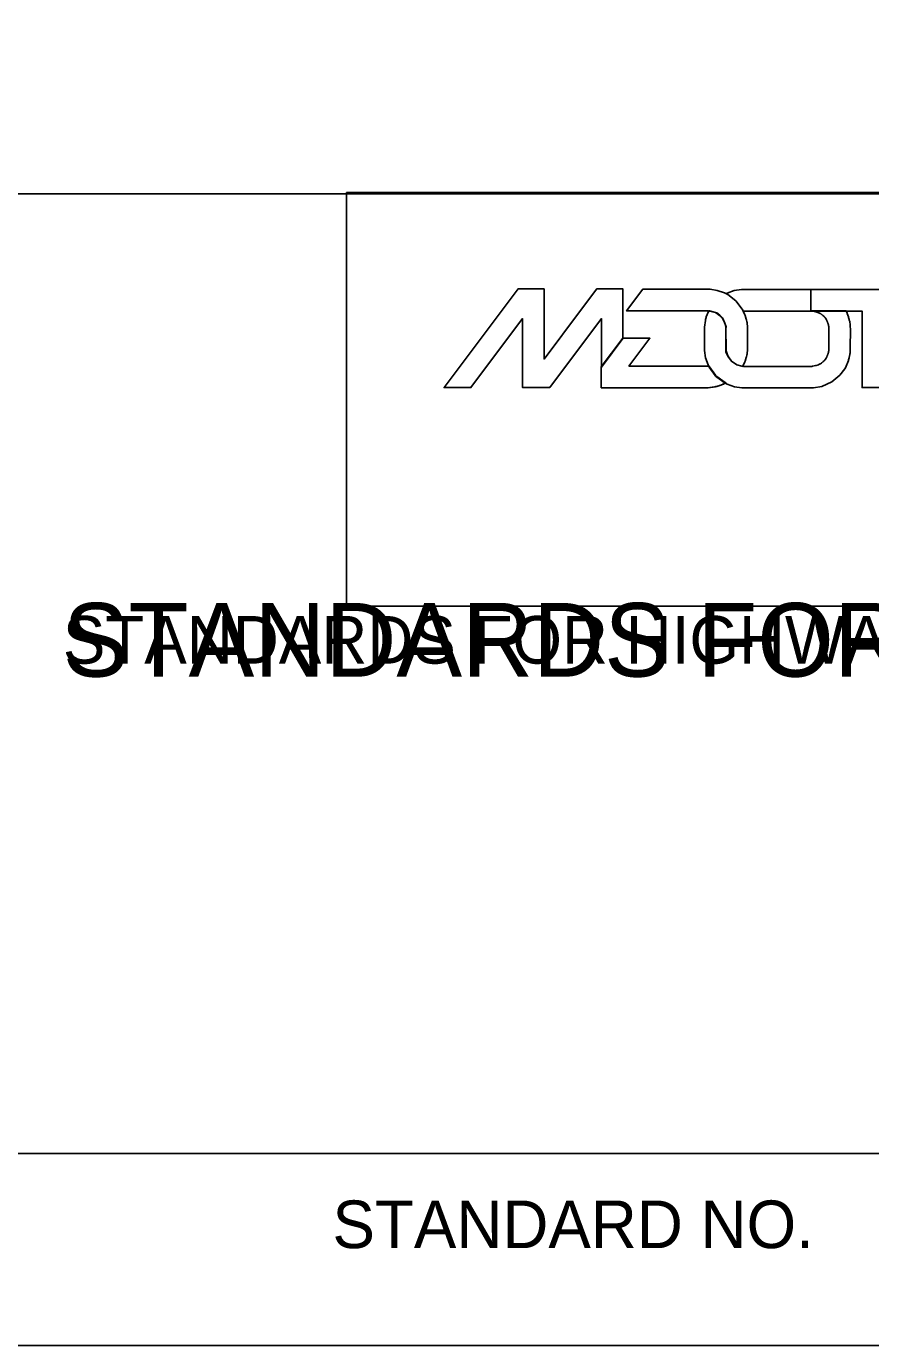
# Model space of a CAD drawing. Extents: x 0 to 1549163, y -476626 to 622136.
# Drawn here: x 3.645 to 4.709, y 5.937 to 7.599 of the extents above; entities that cross this region are included whole.
import ezdxf

# ---------------------------------------------------------------- set-up
doc = ezdxf.new("R2010")
doc.units = 0
for name, color, linetype in [('BORD-LINE', 7, 'Continuous'), ('DETL-NOTE', 7, 'Continuous'), ('MSHA-LOGO', 7, 'Continuous'), ('TTLB-TEXT', 7, 'Continuous'), ('USER-BORD', 7, 'Continuous'), ('USER-LINE', 7, 'Continuous')]:
    doc.layers.add(name, color=color, linetype=linetype)

msp = doc.modelspace()

# ---------------------------------------------------------------- linework, layer by layer
at = {"layer": 'BORD-LINE'}
msp.add_line((7.7685, 7.3883), (0.3943, 7.3883), dxfattribs=at)
at = {"layer": 'MSHA-LOGO'}
for points in [[(4.3697, 7.1699), (4.3968, 7.206), (4.3968, 7.2687), (4.3638, 7.2687), (4.3434, 7.2413), (4.2975, 7.1802), (4.2975, 7.2687), (4.2646, 7.2687), (4.1714, 7.1444), (4.2053, 7.1444), (4.2704, 7.2312), (4.2704, 7.1444), (4.3046, 7.1444), (4.3697, 7.2312)], [(4.5048, 7.2408), (4.5056, 7.2408), (4.5132, 7.2388), (4.5139, 7.2384), (4.5147, 7.238), (4.5185, 7.2352), (4.5217, 7.2319), (4.5223, 7.2312), (4.5229, 7.2303), (4.5251, 7.2256), (4.5263, 7.2205), (4.5264, 7.2195), (4.5264, 7.2195), (4.5264, 7.2193), (4.5264, 7.2193), (4.5264, 7.219), (4.5264, 7.2184), (4.5264, 7.2182), (4.5264, 7.1947), (4.5264, 7.1944), (4.5264, 7.1938), (4.5264, 7.1936), (4.5264, 7.1936), (4.5264, 7.1934), (4.5264, 7.1934), (4.5264, 7.1929), (4.5262, 7.1918), (4.5262, 7.1914), (4.5265, 7.1894), (4.5287, 7.1838), (4.5334, 7.1776), (4.5402, 7.1731), (4.5463, 7.1712), (4.5476, 7.1711), (4.5479, 7.1715), (4.5481, 7.1717), (4.5481, 7.1717), (4.5483, 7.1722), (4.5503, 7.1766), (4.5505, 7.1771), (4.5506, 7.1776), (4.552, 7.1823), (4.5522, 7.1828), (4.5522, 7.183), (4.5528, 7.1854), (4.5529, 7.1857), (4.553, 7.1864), (4.5537, 7.1927), (4.5537, 7.1948), (4.5537, 7.2179), (4.5537, 7.2202), (4.553, 7.2263), (4.5529, 7.227), (4.5528, 7.2273), (4.5523, 7.2297), (4.5522, 7.23), (4.552, 7.2304), (4.5506, 7.2352), (4.5505, 7.2356), (4.5503, 7.2361), (4.5483, 7.2406), (4.5481, 7.241), (4.5468, 7.2433), (4.5389, 7.2535), (4.5287, 7.2615), (4.5264, 7.2627), (4.5247, 7.2636), (4.5155, 7.2668), (4.5066, 7.2682), (4.5036, 7.2682), (4.4217, 7.2682), (4.4013, 7.241), (4.5036, 7.241), (4.5037, 7.2409), (4.5045, 7.2408)], [(4.5482, 7.2406), (4.5487, 7.2406), (4.5489, 7.2406), (4.6329, 7.2406), (4.633, 7.2406), (4.6333, 7.2406), (4.6334, 7.2406), (4.6335, 7.241), (4.6335, 7.268), (4.6335, 7.268), (4.633, 7.268), (4.6329, 7.268), (4.5489, 7.268), (4.5459, 7.268), (4.537, 7.2666), (4.5278, 7.2634), (4.5264, 7.2627), (4.5287, 7.2615), (4.5389, 7.2535), (4.5468, 7.2433), (4.5481, 7.241)], [(4.6335, 7.268), (4.6335, 7.2408), (4.6979, 7.2408), (4.6979, 7.1444), (4.7249, 7.1444), (4.7249, 7.2408), (4.7625, 7.2408), (4.7895, 7.2678), (4.7895, 7.268)], [(4.5269, 7.1499), (4.5268, 7.1499), (4.5266, 7.15), (4.5266, 7.1501), (4.5254, 7.1507), (4.5151, 7.1582), (4.5142, 7.1592), (4.5133, 7.1601), (4.5059, 7.1703), (4.5053, 7.1714), (4.5052, 7.1714), (4.5049, 7.1714), (4.5048, 7.1714), (4.5045, 7.1714), (4.5038, 7.1714), (4.5036, 7.1714), (4.4042, 7.1714), (4.4306, 7.2064), (4.3966, 7.2064), (4.3695, 7.1704), (4.3695, 7.1442), (4.5034, 7.1442), (4.5042, 7.1442), (4.5062, 7.1443), (4.5065, 7.1444), (4.5072, 7.1444), (4.5092, 7.1447), (4.5094, 7.1447), (4.5096, 7.1447), (4.5101, 7.1449), (4.5103, 7.1449), (4.5104, 7.1449), (4.512, 7.1452), (4.5122, 7.1452), (4.5124, 7.1452), (4.513, 7.1454), (4.5132, 7.1454), (4.5133, 7.1455), (4.5148, 7.1457), (4.5149, 7.1457), (4.515, 7.1458), (4.5158, 7.1461), (4.5159, 7.1461), (4.5161, 7.1461), (4.5174, 7.1466), (4.5175, 7.1466), (4.5176, 7.1467), (4.5184, 7.1469), (4.5185, 7.1469), (4.5186, 7.147), (4.5199, 7.1474), (4.5201, 7.1475), (4.5201, 7.1475), (4.521, 7.1478), (4.5211, 7.1478), (4.5212, 7.1479), (4.5227, 7.1485), (4.5228, 7.1485), (4.5229, 7.1485), (4.5236, 7.1488), (4.5237, 7.1489), (4.5239, 7.1489), (4.5259, 7.1499), (4.5261, 7.1501), (4.5262, 7.15), (4.5267, 7.1499)]]:
    msp.add_lwpolyline(points, close=True, dxfattribs=at)
for points in [[(4.5264, 7.205), (4.5264, 7.2179), (4.5264, 7.2183), (4.5264, 7.219), (4.5264, 7.2193), (4.5264, 7.2198), (4.5266, 7.221), (4.5266, 7.2214), (4.5265, 7.2223), (4.5231, 7.2306), (4.5226, 7.2313), (4.5221, 7.2321), (4.5188, 7.2356), (4.5149, 7.2383), (4.5141, 7.2387), (4.5133, 7.2391), (4.5058, 7.2411), (4.505, 7.2412), (4.505, 7.2411), (4.5048, 7.2408), (4.5044, 7.2402), (4.5017, 7.2334), (4.5015, 7.2327), (4.5014, 7.2325), (4.5007, 7.2301), (4.5007, 7.2298), (4.5005, 7.2288), (4.4993, 7.2206), (4.4993, 7.2179), (4.4993, 7.205), (4.4993, 7.2036)], [(4.6832, 7.2179), (4.6832, 7.2186), (4.683, 7.2206), (4.683, 7.2208), (4.683, 7.221), (4.683, 7.2217), (4.683, 7.2222), (4.6828, 7.2234), (4.6828, 7.2238), (4.6828, 7.2239), (4.6828, 7.2242), (4.6828, 7.2243), (4.6828, 7.2244), (4.6828, 7.2246), (4.6828, 7.2246), (4.6828, 7.2248), (4.6825, 7.2265), (4.6825, 7.2267), (4.6825, 7.2269), (4.6823, 7.2273), (4.6823, 7.2274), (4.6823, 7.2276), (4.6818, 7.2294), (4.6818, 7.2296), (4.6818, 7.2298), (4.6818, 7.23), (4.6817, 7.2302), (4.681, 7.2328), (4.6809, 7.2331), (4.6808, 7.2335), (4.6792, 7.2378), (4.679, 7.2382), (4.679, 7.2384), (4.6779, 7.2406), (4.6779, 7.2408), (4.6779, 7.2409), (4.6777, 7.2412), (4.6342, 7.2412), (4.6341, 7.2408), (4.6346, 7.2408), (4.6348, 7.2408), (4.635, 7.2408), (4.6355, 7.2407), (4.6356, 7.2406), (4.636, 7.2406), (4.6394, 7.2399), (4.6397, 7.2398), (4.64, 7.2397), (4.6429, 7.2387), (4.6432, 7.2386), (4.6433, 7.2385), (4.6449, 7.2376), (4.6451, 7.2375), (4.6452, 7.2375), (4.6452, 7.2375), (4.6454, 7.2375), (4.6468, 7.2366), (4.6469, 7.2365), (4.6471, 7.2364), (4.6471, 7.2363), (4.6472, 7.2362), (4.6485, 7.2353), (4.6487, 7.2351), (4.6488, 7.235), (4.649, 7.2349), (4.65, 7.2338), (4.65, 7.2337), (4.6502, 7.2336), (4.6502, 7.2336), (4.6504, 7.2334), (4.6505, 7.2333), (4.6512, 7.2325), (4.6512, 7.2324), (4.6514, 7.2322), (4.6514, 7.2322), (4.6517, 7.2317), (4.6518, 7.2317), (4.6518, 7.2316), (4.6526, 7.2306), (4.6526, 7.2305), (4.6527, 7.2304), (4.6529, 7.2299), (4.653, 7.2298), (4.6531, 7.2296), (4.6531, 7.2296), (4.6532, 7.2295), (4.6536, 7.2287), (4.6536, 7.2286), (4.6537, 7.2285), (4.6539, 7.2278), (4.654, 7.2277), (4.654, 7.2276), (4.6545, 7.2266), (4.6545, 7.2265), (4.6545, 7.2265), (4.6547, 7.2258), (4.6547, 7.2257), (4.6548, 7.2255), (4.6548, 7.2255), (4.6549, 7.2254), (4.6552, 7.2247), (4.6552, 7.2244), (4.6552, 7.2244), (4.6555, 7.2233), (4.6555, 7.2232), (4.6555, 7.223), (4.6557, 7.2224), (4.6557, 7.2222), (4.6557, 7.2221), (4.6559, 7.2211), (4.6559, 7.2208), (4.6559, 7.2206), (4.656, 7.2201), (4.656, 7.22), (4.656, 7.2194), (4.6562, 7.2182), (4.6562, 7.2177), (4.6562, 7.1941), (4.6562, 7.1936), (4.6561, 7.1921), (4.656, 7.1919), (4.656, 7.1917), (4.6559, 7.1911), (4.6559, 7.191), (4.6559, 7.1907), (4.6557, 7.1899), (4.6557, 7.1897), (4.6557, 7.1894), (4.6555, 7.1888), (4.6555, 7.1886), (4.6555, 7.1885), (4.6552, 7.1875), (4.6552, 7.1874), (4.6551, 7.1873), (4.6549, 7.1865), (4.6548, 7.1864), (4.6548, 7.1863), (4.6547, 7.1861), (4.6547, 7.186), (4.6545, 7.1855), (4.6545, 7.1854), (4.6545, 7.1853), (4.654, 7.1843), (4.654, 7.1842), (4.6539, 7.1841), (4.6537, 7.1834), (4.6536, 7.1833), (4.6536, 7.1832), (4.6532, 7.1823), (4.6531, 7.1823), (4.653, 7.1821), (4.653, 7.1821), (4.6529, 7.182), (4.6527, 7.1815), (4.6526, 7.1814), (4.6525, 7.1813), (4.6518, 7.1803), (4.6518, 7.1802), (4.6517, 7.1802), (4.6514, 7.1797), (4.6514, 7.1797), (4.6512, 7.1795), (4.6511, 7.1794), (4.6504, 7.1786), (4.6504, 7.1785), (4.6502, 7.1783), (4.6501, 7.1781), (4.65, 7.1781), (4.65, 7.178), (4.6489, 7.177), (4.6488, 7.1769), (4.6487, 7.1767), (4.6485, 7.1767), (4.6472, 7.1756), (4.6471, 7.1755), (4.6469, 7.1754), (4.6469, 7.1754), (4.6468, 7.1753), (4.6454, 7.1744), (4.6452, 7.1743), (4.6451, 7.1743), (4.6451, 7.1743), (4.6449, 7.1743), (4.6433, 7.1734), (4.6432, 7.1733), (4.6429, 7.1732), (4.64, 7.1722), (4.6397, 7.1721), (4.6394, 7.172), (4.636, 7.1713), (4.6356, 7.1712), (4.6354, 7.1712), (4.6348, 7.1711), (4.6348, 7.1711), (4.6345, 7.1711), (4.6338, 7.1711), (4.6335, 7.1711), (4.5496, 7.1711), (4.5493, 7.1711), (4.5486, 7.1711), (4.5484, 7.1711), (4.5463, 7.1712), (4.5402, 7.1731), (4.5335, 7.1778), (4.5288, 7.1845), (4.5269, 7.1905), (4.5268, 7.1926), (4.5268, 7.1929), (4.5268, 7.1937), (4.5268, 7.194), (4.5268, 7.205), (4.5264, 7.205)], [(4.4993, 7.2036), (4.4993, 7.194), (4.4993, 7.191), (4.5007, 7.182), (4.5039, 7.1728), (4.5048, 7.1711), (4.5054, 7.1699), (4.513, 7.1594), (4.5139, 7.1585), (4.5148, 7.1576), (4.5253, 7.15), (4.5264, 7.1494), (4.5281, 7.1485), (4.5373, 7.1453), (4.5463, 7.1439), (4.5492, 7.1439), (4.6332, 7.1439), (4.6367, 7.1439), (4.6472, 7.1458), (4.6596, 7.1514), (4.6699, 7.16), (4.6761, 7.1681), (4.6777, 7.1711), (4.6778, 7.1713), (4.6788, 7.1734), (4.6789, 7.1736), (4.679, 7.1741), (4.6806, 7.1784), (4.6808, 7.1788), (4.6808, 7.1791), (4.6816, 7.1817), (4.6816, 7.1819), (4.6816, 7.1821), (4.6816, 7.1823), (4.6817, 7.1824), (4.6821, 7.1843), (4.6821, 7.1845), (4.6821, 7.1847), (4.6823, 7.1851), (4.6823, 7.1852), (4.6823, 7.1854), (4.6826, 7.1871), (4.6827, 7.1872), (4.6827, 7.1873), (4.6827, 7.1875), (4.6827, 7.1876), (4.6827, 7.1877), (4.6827, 7.188), (4.6827, 7.1881), (4.6827, 7.1886), (4.6828, 7.1898), (4.6828, 7.1902), (4.6828, 7.1909), (4.6828, 7.191), (4.6828, 7.1918), (4.683, 7.1934), (4.683, 7.194), (4.6832, 7.2179)]]:
    msp.add_lwpolyline(points, dxfattribs=at)
at = {"layer": 'TTLB-TEXT'}
msp.add_line((7.7685, 7.3883), (0.3943, 7.3883), dxfattribs=at)
msp.add_lwpolyline([(0.3943, 16.2906), (7.7685, 16.2906), (7.7685, 5.9375), (0.3943, 5.9375)], close=True, dxfattribs=at)
at = {"layer": 'USER-BORD'}
for p, q in [((7.7685, 7.3883), (0.3943, 7.3883)), ((3.2956, 6.1793), (7.7685, 6.1793))]:
    msp.add_line(p, q, dxfattribs=at)
at = {"layer": 'USER-LINE'}
msp.add_lwpolyline([(7.0197, 6.8692), (4.0486, 6.8692), (4.0486, 7.3899), (7.0197, 7.3899)], close=True, dxfattribs=at)

# ---------------------------------------------------------------- texts
at = {"layer": 'DETL-NOTE'}
msp.add_text('STANDARDS FOR HIGHWAYS AND INCIDENTAL STRUCTURES', height=0.09269, dxfattribs=at).set_placement((3.6914, 6.7803))
at = {"layer": 'TTLB-TEXT'}
for s, height, p in [('STANDARDS FOR HIGHWAYS AND INCIDENTAL STRUCTURES', 0.09269, (3.6913, 6.7802)), ('STANDARDS FOR HIGHWAYS AND INCIDENTAL STRUCTURES', 0.06, (3.6914, 6.7966)), ('STANDARD NO.', 0.06, (4.0309, 6.0603))]:
    msp.add_text(s, height=height, dxfattribs=at).set_placement(p)

doc.saveas('drawing.dxf')
